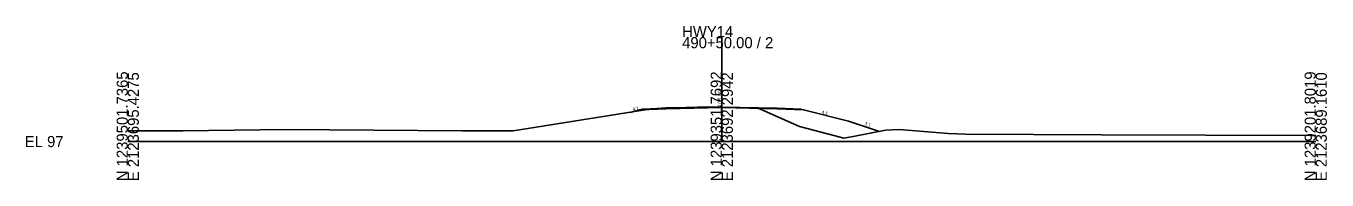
# Model space of a CAD drawing. Extents: x -26 to 303, y -10 to 11521.
# Drawn here: x -25.7 to 302.8, y 1990.3 to 2029.1 of the extents above; entities that cross this region are included whole.
import ezdxf

# ---------------------------------------------------------------- set-up
doc = ezdxf.new("R2010")
doc.units = 0
for name, color, linetype in [('XS_CELL', 7, 'Continuous'), ('XS_P_FINISHED_GRADE', 7, 'Continuous'), ('XS_P_SUBGRADE_GRANULAR', 7, 'Continuous'), ('XS_P_SUBGRADE_LEVELING', 7, 'Continuous'), ('XS_P_TX_FS_BS', 7, 'Continuous'), ('XS_X_GROUND', 7, 'Continuous'), ('XS_X_GROUND_TX', 7, 'Continuous')]:
    doc.layers.add(name, color=color, linetype=linetype)

msp = doc.modelspace()

# ---------------------------------------------------------------- linework, layer by layer
at = {"layer": 'XS_CELL'}
for p, q in [((150, 2000), (150, 2026.35)), ((0, 2000), (150, 2000)), ((150, 2000), (300, 2000))]:
    msp.add_line(p, q, dxfattribs=at)
at = {"layer": 'XS_P_FINISHED_GRADE'}
for p, q in [((130, 2008.17), (126.77, 2007.36)), ((136, 2008.41), (130, 2008.17)), ((150, 2008.69), (136, 2008.41)), ((150, 2008.69), (164, 2008.41)), ((164, 2008.41), (170, 2008.17)), ((170, 2008.17), (182, 2005.17)), ((182, 2005.17), (189.82, 2002.57))]:
    msp.add_line(p, q, dxfattribs=at)
at = {"layer": 'XS_P_SUBGRADE_GRANULAR'}
for p, q in [((136, 2008.29), (129.4, 2008.02)), ((164, 2008.29), (170.6, 2008.02))]:
    msp.add_line(p, q, dxfattribs=at)
at = {"layer": 'XS_P_SUBGRADE_LEVELING'}
for p, q in [((150, 2008.57), (136, 2008.29)), ((136, 2008.29), (136, 2008.41)), ((150, 2008.57), (164, 2008.29)), ((164, 2008.29), (164, 2008.41))]:
    msp.add_line(p, q, dxfattribs=at)
at = {"layer": 'XS_X_GROUND'}
for p, q in [((97.32, 2002.71), (129.59, 2007.81)), ((129.59, 2007.81), (132.58, 2008.28)), ((132.58, 2008.28), (135.84, 2008.5)), ((135.84, 2008.5), (140.96, 2008.63)), ((140.96, 2008.63), (146.76, 2008.78)), ((146.76, 2008.78), (150, 2008.69)), ((150, 2008.69), (154.66, 2008.56)), ((154.66, 2008.56), (157.78, 2008.49)), ((157.78, 2008.49), (159.59, 2008.26)), ((159.59, 2008.26), (159.95, 2008.11)), ((159.95, 2008.11), (169.66, 2003.83)), ((0, 2002.71), (13.92, 2002.73)), ((13.92, 2002.73), (39.87, 2003.07)), ((39.87, 2003.07), (84.34, 2002.71)), ((84.34, 2002.71), (97.32, 2002.71)), ((169.66, 2003.83), (178.33, 2001.49)), ((178.33, 2001.49), (180.82, 2000.82)), ((180.82, 2000.82), (183.17, 2001.29)), ((183.17, 2001.29), (191.38, 2002.87)), ((191.38, 2002.87), (194.78, 2003.02)), ((194.78, 2003.02), (207.15, 2002.07)), ((207.15, 2002.07), (211.55, 2001.86)), ((211.55, 2001.86), (245.88, 2001.68)), ((245.88, 2001.68), (298.56, 2001.53)), ((298.56, 2001.53), (300, 2001.54))]:
    msp.add_line(p, q, dxfattribs=at)

# ---------------------------------------------------------------- texts
at = {"layer": 'XS_CELL'}
for s, p in [('HWY14', (140, 2026.35)), ('490+50.00 / 2', (140, 2023.55)), ('EL 97', (-26, 1998.6))]:
    msp.add_text(s, height=2.8, dxfattribs=at).set_placement(p)
for s, p in [('N 1239501.7365', (0, 1990)), ('E 2123695.4275', (2.8, 1990)), ('N 1239351.7692', (150, 1990)), ('E 2123692.2942', (152.8, 1990)), ('N 1239201.8019', (300, 1990)), ('E 2123689.1610', (302.8, 1990))]:
    msp.add_text(s, height=2.8, rotation=90, dxfattribs=at).set_placement(p)
at = {"layer": 'XS_P_TX_FS_BS'}
for s, rotation, p in [('4:1', 14.0362, (127.6, 2007.72)), ('4:1', 345.9638, (175.22, 2007.07)), ('3:1', 341.5651, (186.02, 2004.2))]:
    msp.add_text(s, height=0.8, rotation=rotation, dxfattribs=at).set_placement(p)
at = {"layer": 'XS_X_GROUND_TX'}
msp.add_text('105.69', height=1, rotation=90, dxfattribs=at).set_placement((150, 2008.79))

doc.saveas('drawing.dxf')
